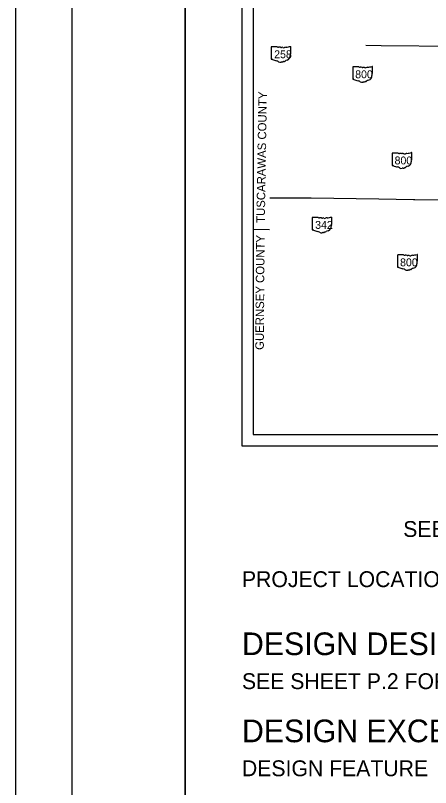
# Model space of a CAD drawing. Extents: x 0 to 34, y -32.5 to 22.
# Drawn here: x 0 to 3.67, y 10.98 to 17.8 of the extents above; entities that cross this region are included whole.
import ezdxf

# ---------------------------------------------------------------- set-up
doc = ezdxf.new("R2010")
doc.units = 0
for name, color, linetype in [('GM_X_Adjacent_County', 7, 'Continuous'), ('GM_X_County', 7, 'Continuous'), ('GM_X_County_Road_Text', 7, 'Continuous'), ('GM_X_County_ROW', 7, 'Continuous'), ('GM_X_Minor_River', 7, 'Continuous'), ('GM_X_Minor_River_Text', 7, 'Continuous'), ('GM_X_Section', 7, 'Continuous'), ('GM_X_Township', 7, 'Continuous')]:
    doc.layers.add(name, color=color, linetype=linetype)

msp = doc.modelspace()

# ---------------------------------------------------------------- linework, layer by layer
at = {"layer": 'GM_X_County'}
for points in [[(0.5, 21.5), (1.5, 21.5), (1.5, 0.5), (0.5, 0.5)], [(1.5, 21.5), (33.5, 21.5), (33.5, 0.5), (1.5, 0.5)]]:
    msp.add_lwpolyline(points, close=True, dxfattribs=at)
at = {"layer": 'GM_X_County_Road_Text'}
msp.add_line((2.2444, 15.9047), (2.1, 15.9082), dxfattribs=at)
at = {"layer": 'GM_X_County_ROW'}
msp.add_lwpolyline([(3.0949, 17.5354), (3.2293, 17.5323), (3.8985, 17.5258), (3.8919, 17.1439), (3.8881, 16.941), (3.8731, 16.2596), (3.8722, 16.2095), (3.8718, 16.1665), (3.7972, 16.1673), (3.5262, 16.1718), (3.5138, 16.1719), (3.2094, 16.176), (2.6123, 16.1865), (2.2906, 16.1847), (2.2448, 16.1852)], dxfattribs=at)
at = {"layer": 'GM_X_Minor_River_Text'}
for p, q in [((2.2584, 17.5187), (2.2584, 17.413)), ((2.3111, 17.5205), (2.2601, 17.5205)), ((2.4325, 17.4679), (2.4325, 17.5231)), ((2.4324, 17.4679), (2.4325, 17.4679)), ((2.9785, 17.342), (2.9785, 17.2364)), ((3.0312, 17.3439), (2.9802, 17.3439)), ((3.1525, 17.2912), (3.1525, 17.3465)), ((3.1525, 17.2912), (3.1525, 17.2912)), ((3.3263, 16.5817), (3.3263, 16.4761)), ((3.379, 16.5835), (3.328, 16.5835)), ((3.5003, 16.5309), (3.5003, 16.5862)), ((3.5003, 16.5309), (3.5003, 16.5309)), ((2.6206, 16.013), (2.6206, 15.9074)), ((2.6732, 16.0148), (2.6223, 16.0148)), ((2.7946, 15.9622), (2.7946, 16.0175)), ((2.7946, 15.9622), (2.7946, 15.9622)), ((3.3749, 15.6826), (3.3749, 15.5769)), ((3.4276, 15.6844), (3.3766, 15.6844)), ((3.549, 15.6317), (3.549, 15.687)), ((3.5489, 15.6318), (3.549, 15.6317))]:
    msp.add_line(p, q, dxfattribs=at)
for centre, major_axis, start_param, end_param in [((2.2604, 17.5189), (0.00202, 0), 1.712693, 3.28349), ((2.3232, 17.5328), (0.0196, 0), 4.042523, 4.731795), ((2.3297, 17.4612), (0.0702, 0), 1.404758, 1.657858), ((2.3457, 17.5195), (0.00564, 0), 3.836095, 5.185415), ((2.3539, 17.5073), (0.0117, 0), 0.950623, 2.079405), ((2.3691, 17.524), (0.0141, 0), 4.081561, 5.145723), ((2.394, 17.4882), (0.0371, 0), 1.699011, 2.107814), ((2.3705, 17.6646), (0.1845, 0), 4.814394, 5.042369), ((2.4305, 17.5234), (0.00194, 0), 6.141152, 7.989035), ((2.3808, 17.4377), (0.0462, 0), 5.101752, 6.440018), ((2.4394, 17.4447), (0.0131, 0), 2.387724, 3.262537), ((2.432, 17.4638), (0.003, 0), 1.883978, 3.671073), ((2.4129, 17.4568), (0.018, 0), 5.934695, 6.695948), ((2.4304, 17.4676), (0.00207, 0), 5.05454, 6.418171), ((2.2604, 17.4128), (0.00203, 0), 3.00124, 4.508301), ((2.2608, 17.4236), (0.0155, 0), 4.665946, 4.897461), ((2.2639, 17.4069), (0.0056, 0), 0.519207, 1.627899), ((2.3346, 17.5019), (0.1333, 0), 4.195997, 4.488961), ((2.2949, 17.3656), (0.0417, 0), 0.823519, 1.323587), ((2.34, 17.4064), (0.0265, 0), 4.026481, 4.996735), ((2.3552, 17.3699), (0.0217, 0), 1.495662, 1.94098), ((2.3572, 17.3985), (0.0141, 0), 4.691044, 5.507374), ((2.3699, 17.3883), (0.00397, 0), 1.147584, 2.315152), ((2.3682, 17.4028), (0.0149, 0), 4.937069, 5.64225), ((2.4003, 17.3834), (0.0253, 0), 1.647645, 2.488434), ((2.9805, 17.3423), (0.00202, 0), 1.712693, 3.28349), ((3.0433, 17.3561), (0.0196, 0), 4.042523, 4.731795), ((3.0498, 17.2845), (0.0702, 0), 1.404758, 1.657858), ((3.0657, 17.3428), (0.00564, 0), 3.836095, 5.185415), ((3.074, 17.3306), (0.0117, 0), 0.950623, 2.079405), ((3.0891, 17.3474), (0.0141, 0), 4.081561, 5.145723), ((3.1141, 17.3116), (0.0371, 0), 1.699011, 2.107814), ((3.0905, 17.4879), (0.1845, 0), 4.814394, 5.042369), ((3.1506, 17.3467), (0.00194, 0), 6.141152, 7.989035), ((3.1009, 17.261), (0.0462, 0), 5.101752, 6.440018), ((3.1595, 17.2681), (0.0131, 0), 2.387724, 3.262537), ((3.1521, 17.2871), (0.003, 0), 1.883978, 3.671073), ((3.133, 17.2802), (0.018, 0), 5.934695, 6.695948), ((3.1504, 17.291), (0.00207, 0), 5.05454, 6.418171), ((2.9805, 17.2361), (0.00203, 0), 3.00124, 4.508301), ((2.9808, 17.247), (0.0155, 0), 4.665946, 4.897461), ((2.984, 17.2303), (0.0056, 0), 0.519207, 1.627899), ((3.0546, 17.3252), (0.1333, 0), 4.195997, 4.488961), ((3.0149, 17.1889), (0.0417, 0), 0.823519, 1.323587), ((3.06, 17.2298), (0.0265, 0), 4.026481, 4.996735), ((3.0753, 17.1932), (0.0217, 0), 1.495662, 1.94098), ((3.0772, 17.2218), (0.0141, 0), 4.691044, 5.507374), ((3.09, 17.2116), (0.00397, 0), 1.147584, 2.315152), ((3.0883, 17.2261), (0.0149, 0), 4.937069, 5.64225), ((3.1203, 17.2067), (0.0253, 0), 1.647645, 2.488434), ((3.3283, 16.5819), (0.00202, 0), 1.712693, 3.28349), ((3.3911, 16.5958), (0.0196, 0), 4.042523, 4.731795), ((3.3976, 16.5242), (0.0702, 0), 1.404758, 1.657858), ((3.4135, 16.5825), (0.00564, 0), 3.836095, 5.185415), ((3.4218, 16.5703), (0.0117, 0), 0.950623, 2.079405), ((3.437, 16.587), (0.0141, 0), 4.081561, 5.145723), ((3.4619, 16.5513), (0.0371, 0), 1.699011, 2.107814), ((3.4383, 16.7276), (0.1845, 0), 4.814394, 5.042369), ((3.4984, 16.5864), (0.00194, 0), 6.141152, 7.989035), ((3.4487, 16.5007), (0.0462, 0), 5.101752, 6.440018), ((3.5073, 16.5078), (0.0131, 0), 2.387724, 3.262537), ((3.4999, 16.5268), (0.003, 0), 1.883978, 3.671073), ((3.4808, 16.5198), (0.018, 0), 5.934695, 6.695948), ((3.4983, 16.5307), (0.00207, 0), 5.05454, 6.418171), ((3.3283, 16.4758), (0.00203, 0), 3.00124, 4.508301), ((3.3286, 16.4866), (0.0155, 0), 4.665946, 4.897461), ((3.3318, 16.47), (0.0056, 0), 0.519207, 1.627899), ((3.4025, 16.5649), (0.1333, 0), 4.195997, 4.488961), ((3.3627, 16.4286), (0.0417, 0), 0.823519, 1.323587), ((3.4078, 16.4694), (0.0265, 0), 4.026481, 4.996735), ((3.4231, 16.4329), (0.0217, 0), 1.495662, 1.94098), ((3.4251, 16.4615), (0.0141, 0), 4.691044, 5.507374), ((3.4378, 16.4513), (0.00397, 0), 1.147584, 2.315152), ((3.4361, 16.4658), (0.0149, 0), 4.937069, 5.64225), ((3.4681, 16.4464), (0.0253, 0), 1.647645, 2.488434), ((2.6225, 16.0132), (0.00202, 0), 1.712693, 3.28349), ((2.6854, 16.0271), (0.0196, 0), 4.042523, 4.731795), ((2.7326, 16.1589), (0.1845, 0), 4.814394, 5.042369), ((2.7926, 16.0177), (0.00194, 0), 6.141152, 7.989035), ((2.6918, 15.9555), (0.0702, 0), 1.404758, 1.657858), ((2.7078, 16.0138), (0.00564, 0), 3.836095, 5.185415), ((2.7161, 16.0016), (0.0117, 0), 0.950623, 2.079405), ((2.7312, 16.0183), (0.0141, 0), 4.081561, 5.145723), ((2.7561, 15.9826), (0.0371, 0), 1.699011, 2.107814), ((2.8015, 15.9391), (0.0131, 0), 2.387724, 3.262537), ((2.7941, 15.9581), (0.003, 0), 1.883978, 3.671073), ((2.7751, 15.9511), (0.018, 0), 5.934695, 6.695948), ((2.7925, 15.962), (0.00207, 0), 5.05454, 6.418171), ((2.6226, 15.9071), (0.00203, 0), 3.00124, 4.508301), ((2.6229, 15.9179), (0.0155, 0), 4.665946, 4.897461), ((2.626, 15.9013), (0.0056, 0), 0.519207, 1.627899), ((2.6967, 15.9962), (0.1333, 0), 4.195997, 4.488961), ((2.657, 15.8599), (0.0417, 0), 0.823519, 1.323587), ((2.7021, 15.9007), (0.0265, 0), 4.026481, 4.996735), ((2.7174, 15.8642), (0.0217, 0), 1.495662, 1.94098), ((2.7193, 15.8928), (0.0141, 0), 4.691044, 5.507374), ((2.732, 15.8826), (0.00397, 0), 1.147584, 2.315152), ((2.7304, 15.8971), (0.0149, 0), 4.937069, 5.64225), ((2.7624, 15.8777), (0.0253, 0), 1.647645, 2.488434), ((2.7429, 15.932), (0.0462, 0), 5.101752, 6.440018), ((3.3769, 15.6828), (0.00202, 0), 1.712693, 3.28349), ((3.4397, 15.6967), (0.0196, 0), 4.042523, 4.731795), ((3.4462, 15.6251), (0.0702, 0), 1.404758, 1.657858), ((3.4622, 15.6834), (0.00564, 0), 3.836095, 5.185415), ((3.4704, 15.6711), (0.0117, 0), 0.950623, 2.079405), ((3.4856, 15.6879), (0.0141, 0), 4.081561, 5.145723), ((3.5105, 15.6521), (0.0371, 0), 1.699011, 2.107814), ((3.487, 15.8285), (0.1845, 0), 4.814394, 5.042369), ((3.547, 15.6872), (0.00194, 0), 6.141152, 7.989035), ((3.4973, 15.6016), (0.0462, 0), 5.101752, 6.440018), ((3.5559, 15.6086), (0.0131, 0), 2.387724, 3.262537), ((3.5485, 15.6277), (0.003, 0), 1.883978, 3.671073), ((3.5294, 15.6207), (0.018, 0), 5.934695, 6.695948), ((3.5469, 15.6315), (0.00207, 0), 5.05454, 6.418171), ((3.3769, 15.5767), (0.00203, 0), 3.00124, 4.508301), ((3.3773, 15.5875), (0.0155, 0), 4.665946, 4.897461), ((3.3804, 15.5708), (0.0056, 0), 0.519207, 1.627899), ((3.4511, 15.6658), (0.1333, 0), 4.195997, 4.488961), ((3.4114, 15.5295), (0.0417, 0), 0.823519, 1.323587), ((3.4565, 15.5703), (0.0265, 0), 4.026481, 4.996735), ((3.4717, 15.5338), (0.0217, 0), 1.495662, 1.94098), ((3.4737, 15.5624), (0.0141, 0), 4.691044, 5.507374), ((3.4864, 15.5522), (0.00397, 0), 1.147584, 2.315152), ((3.4847, 15.5667), (0.0149, 0), 4.937069, 5.64225), ((3.5168, 15.5473), (0.0253, 0), 1.647645, 2.488434)]:
    msp.add_ellipse(centre, major_axis=major_axis, ratio=0.8, start_param=start_param, end_param=end_param, dxfattribs=at)
at = {"layer": 'GM_X_Section'}
msp.add_lwpolyline([(0, 0), (34, 0), (34, 22), (0, 22)], close=True, dxfattribs=at)
at = {"layer": 'GM_X_Township'}
for p, q in [((2, 21), (2, 14)), ((2.1, 20.9), (2.1, 14.1)), ((2.1, 14.1), (8.9, 14.1)), ((2.1, 14.1), (2.1, 14.1)), ((2, 14), (9, 14))]:
    msp.add_line(p, q, dxfattribs=at)

# ---------------------------------------------------------------- texts
at = {"layer": 'GM_X_Adjacent_County'}
for s, p in [('SEE SHEET P.2 FOR CULVERT LOCATIONS', (3.4239, 13.1959)), ('PROJECT LOCATIONS', (2, 12.7531)), ('DESIGN FEATURE', (2, 11.0843))]:
    msp.add_text(s, height=0.14, dxfattribs=at).set_placement(p)
at = {"layer": 'GM_X_Minor_River'}
for s, rotation, p in [('TUSCARAWAS COUNTY', 89.04481, (2.2017, 15.9666)), ('GUERNSEY COUNTY', 89.56996, (2.1926, 14.8463))]:
    msp.add_text(s, height=0.075, rotation=rotation, dxfattribs=at).set_placement(p)
at = {"layer": 'GM_X_Minor_River_Text'}
for s, p in [('258', (2.285, 17.4205)), ('800', (3, 17.2438)), ('800', (3.3478, 16.4835)), ('342', (2.6465, 15.9148)), ('800', (3.3965, 15.5844))]:
    msp.add_text(s, height=0.06961, dxfattribs=at).set_placement(p)
at = {"layer": 'GM_X_Township'}
for s, height, p in [('DESIGN DESIGNATION', 0.2, (2, 12.1531)), ('SEE SHEET P.2 FOR DESIGN DESIGNATIONS', 0.14, (2, 11.8531)), ('DESIGN EXCEPTIONS', 0.2, (2, 11.3843))]:
    msp.add_text(s, height=height, dxfattribs=at).set_placement(p)

doc.saveas('drawing.dxf')
